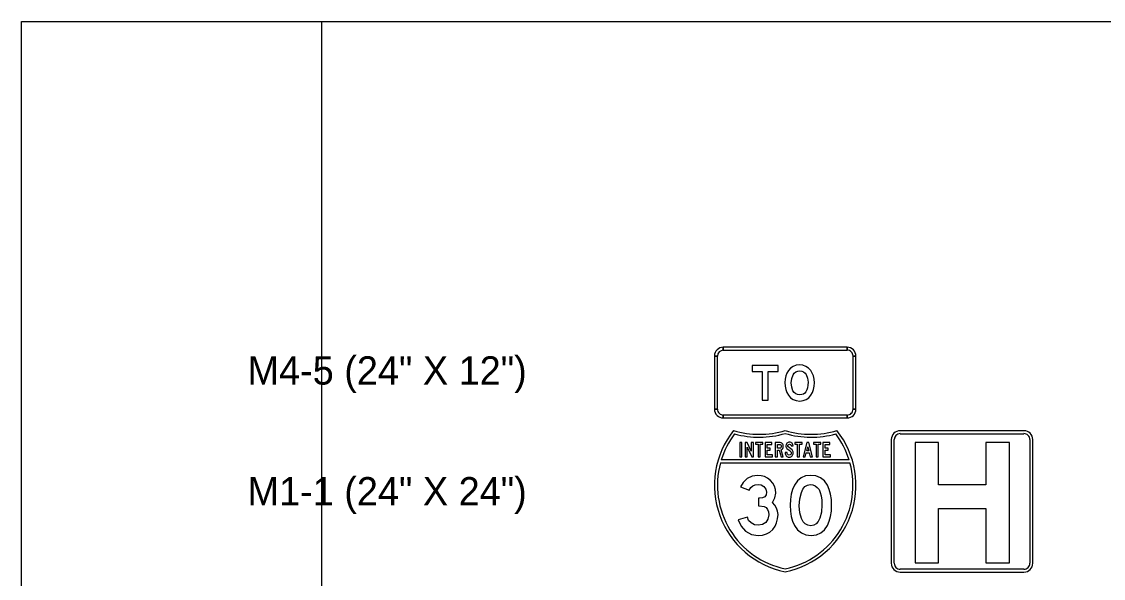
# Model space of a CAD drawing. Extents: x 1001568 to 1002149, y 1840825 to 1841423.
# Drawn here: x 1001886.41 to 1001901.7, y 1841302.79 to 1841310.67 of the extents above; entities that cross this region are included whole.
import ezdxf

# ---------------------------------------------------------------- set-up
doc = ezdxf.new("R2010")
doc.units = 0
for name, color, linetype in [('40', 7, 'Continuous'), ('R_No Plot', 7, 'Continuous'), ('SIGNS', 7, 'Continuous')]:
    doc.layers.add(name, color=color, linetype=linetype)

msp = doc.modelspace()

# ---------------------------------------------------------------- linework, layer by layer
at = {"layer": 'R_No Plot'}
msp.add_line((1001890.65, 1841310.667), (1001890.65, 1841248.127), dxfattribs=at)
msp.add_lwpolyline([(1001886.411, 1841310.667), (1001964.232, 1841310.667), (1001964.232, 1841307.694), (1001968.454, 1841307.694), (1001968.454, 1841306.882), (1001982.133, 1841306.882), (1001982.133, 1841248.127), (1001886.411, 1841248.127)], close=True, dxfattribs=at)
at = {"layer": 'SIGNS'}
for p, q in [((1001898.081, 1841306.062), (1001896.331, 1841306.062)), ((1001896.331, 1841306.02), (1001896.331, 1841306.062)), ((1001898.081, 1841306.062), (1001898.081, 1841306.02)), ((1001896.206, 1841305.937), (1001896.206, 1841305.187)), ((1001896.206, 1841305.937), (1001896.247, 1841305.937)), ((1001898.164, 1841305.937), (1001898.206, 1841305.937)), ((1001898.206, 1841305.187), (1001898.206, 1841305.937)), ((1001896.247, 1841305.187), (1001896.206, 1841305.187)), ((1001896.331, 1841305.062), (1001896.331, 1841305.103)), ((1001898.081, 1841305.103), (1001898.081, 1841305.062)), ((1001898.206, 1841305.187), (1001898.164, 1841305.187)), ((1001896.331, 1841305.062), (1001898.081, 1841305.062)), ((1001900.581, 1841304.882), (1001898.831, 1841304.882)), ((1001900.581, 1841304.882), (1001898.831, 1841304.882)), ((1001898.831, 1841304.84), (1001900.581, 1841304.84)), ((1001896.594, 1841304.715), (1001896.565, 1841304.715)), ((1001896.565, 1841304.715), (1001896.565, 1841304.511)), ((1001896.594, 1841304.511), (1001896.594, 1841304.715)), ((1001896.668, 1841304.715), (1001896.64, 1841304.715)), ((1001896.64, 1841304.715), (1001896.64, 1841304.511)), ((1001896.724, 1841304.593), (1001896.668, 1841304.715)), ((1001896.668, 1841304.511), (1001896.668, 1841304.649)), ((1001896.668, 1841304.649), (1001896.733, 1841304.511)), ((1001896.756, 1841304.715), (1001896.724, 1841304.715)), ((1001896.724, 1841304.715), (1001896.724, 1841304.593)), ((1001896.756, 1841304.511), (1001896.756, 1841304.715)), ((1001896.891, 1841304.715), (1001896.786, 1841304.715)), ((1001896.786, 1841304.715), (1001896.786, 1841304.69)), ((1001896.786, 1841304.69), (1001896.823, 1841304.69)), ((1001896.823, 1841304.69), (1001896.823, 1841304.511)), ((1001896.853, 1841304.511), (1001896.853, 1841304.69)), ((1001896.853, 1841304.69), (1001896.891, 1841304.69)), ((1001896.891, 1841304.69), (1001896.891, 1841304.715)), ((1001897.019, 1841304.715), (1001896.921, 1841304.715)), ((1001896.921, 1841304.715), (1001896.921, 1841304.511)), ((1001896.951, 1841304.635), (1001896.951, 1841304.687)), ((1001896.951, 1841304.687), (1001897.019, 1841304.687)), ((1001896.994, 1841304.635), (1001896.951, 1841304.635)), ((1001896.994, 1841304.607), (1001896.994, 1841304.635)), ((1001897.019, 1841304.687), (1001897.019, 1841304.715)), ((1001897.218, 1841304.686), (1001897.214, 1841304.667)), ((1001897.214, 1841304.667), (1001897.215, 1841304.656)), ((1001897.215, 1841304.656), (1001897.218, 1841304.647)), ((1001897.229, 1841304.704), (1001897.218, 1841304.686)), ((1001897.218, 1841304.647), (1001897.223, 1841304.638)), ((1001897.223, 1841304.638), (1001897.23, 1841304.63)), ((1001897.237, 1841304.71), (1001897.229, 1841304.704)), ((1001897.23, 1841304.63), (1001897.263, 1841304.607)), ((1001897.246, 1841304.715), (1001897.237, 1841304.71)), ((1001897.242, 1841304.667), (1001897.244, 1841304.676)), ((1001897.244, 1841304.661), (1001897.242, 1841304.667)), ((1001897.244, 1841304.676), (1001897.25, 1841304.684)), ((1001897.247, 1841304.655), (1001897.244, 1841304.661)), ((1001897.256, 1841304.718), (1001897.246, 1841304.715)), ((1001897.263, 1841304.643), (1001897.247, 1841304.655)), ((1001897.25, 1841304.684), (1001897.258, 1841304.689)), ((1001897.266, 1841304.719), (1001897.256, 1841304.718)), ((1001897.258, 1841304.689), (1001897.267, 1841304.691)), ((1001897.286, 1841304.627), (1001897.263, 1841304.643)), ((1001897.278, 1841304.718), (1001897.266, 1841304.719)), ((1001897.267, 1841304.691), (1001897.277, 1841304.689)), ((1001897.277, 1841304.689), (1001897.285, 1841304.685)), ((1001897.288, 1841304.716), (1001897.278, 1841304.718)), ((1001897.285, 1841304.685), (1001897.289, 1841304.678)), ((1001897.302, 1841304.613), (1001897.286, 1841304.627)), ((1001897.297, 1841304.711), (1001897.288, 1841304.716)), ((1001897.289, 1841304.678), (1001897.292, 1841304.667)), ((1001897.292, 1841304.667), (1001897.32, 1841304.667)), ((1001897.305, 1841304.705), (1001897.297, 1841304.711)), ((1001897.315, 1841304.688), (1001897.305, 1841304.705)), ((1001897.32, 1841304.667), (1001897.315, 1841304.688)), ((1001897.445, 1841304.715), (1001897.34, 1841304.715)), ((1001897.34, 1841304.715), (1001897.34, 1841304.69)), ((1001897.34, 1841304.69), (1001897.377, 1841304.69)), ((1001897.377, 1841304.69), (1001897.377, 1841304.511)), ((1001897.407, 1841304.511), (1001897.407, 1841304.69)), ((1001897.407, 1841304.69), (1001897.445, 1841304.69)), ((1001897.445, 1841304.69), (1001897.445, 1841304.715)), ((1001897.71, 1841304.715), (1001897.605, 1841304.715)), ((1001897.605, 1841304.715), (1001897.605, 1841304.69)), ((1001897.605, 1841304.69), (1001897.642, 1841304.69)), ((1001897.642, 1841304.69), (1001897.642, 1841304.511)), ((1001897.672, 1841304.511), (1001897.672, 1841304.69)), ((1001897.672, 1841304.69), (1001897.71, 1841304.69)), ((1001897.71, 1841304.69), (1001897.71, 1841304.715)), ((1001897.837, 1841304.715), (1001897.74, 1841304.715)), ((1001897.74, 1841304.715), (1001897.74, 1841304.511)), ((1001897.77, 1841304.635), (1001897.77, 1841304.687)), ((1001897.77, 1841304.687), (1001897.837, 1841304.687)), ((1001897.813, 1841304.635), (1001897.77, 1841304.635)), ((1001897.813, 1841304.607), (1001897.813, 1841304.635)), ((1001897.837, 1841304.687), (1001897.837, 1841304.715)), ((1001898.706, 1841304.757), (1001898.706, 1841303.007)), ((1001898.706, 1841304.757), (1001898.706, 1841303.007)), ((1001898.747, 1841303.007), (1001898.747, 1841304.757)), ((1001899.375, 1841304.715), (1001899.042, 1841304.715)), ((1001899.042, 1841304.715), (1001899.042, 1841303.015)), ((1001899.375, 1841304.715), (1001899.042, 1841304.715)), ((1001899.042, 1841304.715), (1001899.042, 1841303.015)), ((1001899.375, 1841304.115), (1001899.375, 1841304.715)), ((1001899.375, 1841304.115), (1001899.375, 1841304.715)), ((1001900.375, 1841304.715), (1001900.042, 1841304.715)), ((1001900.042, 1841304.715), (1001900.042, 1841304.115)), ((1001900.375, 1841304.715), (1001900.042, 1841304.715)), ((1001900.042, 1841304.715), (1001900.042, 1841304.115)), ((1001900.375, 1841303.015), (1001900.375, 1841304.715)), ((1001900.375, 1841303.015), (1001900.375, 1841304.715)), ((1001900.664, 1841304.757), (1001900.664, 1841303.007)), ((1001900.706, 1841303.007), (1001900.706, 1841304.757)), ((1001900.706, 1841303.007), (1001900.706, 1841304.757)), ((1001898.11, 1841304.469), (1001896.302, 1841304.469)), ((1001896.565, 1841304.511), (1001896.594, 1841304.511)), ((1001896.64, 1841304.511), (1001896.668, 1841304.511)), ((1001896.733, 1841304.511), (1001896.756, 1841304.511)), ((1001896.823, 1841304.511), (1001896.853, 1841304.511)), ((1001896.921, 1841304.511), (1001897.026, 1841304.511)), ((1001896.951, 1841304.539), (1001896.951, 1841304.607)), ((1001896.951, 1841304.607), (1001896.994, 1841304.607)), ((1001897.026, 1841304.539), (1001896.951, 1841304.539)), ((1001897.026, 1841304.511), (1001897.026, 1841304.539)), ((1001897.233, 1841304.572), (1001897.205, 1841304.572)), ((1001897.205, 1841304.572), (1001897.205, 1841304.571)), ((1001897.205, 1841304.571), (1001897.206, 1841304.558)), ((1001897.206, 1841304.558), (1001897.209, 1841304.547)), ((1001897.209, 1841304.547), (1001897.214, 1841304.536)), ((1001897.214, 1841304.536), (1001897.221, 1841304.526)), ((1001897.221, 1841304.526), (1001897.229, 1841304.518)), ((1001897.229, 1841304.518), (1001897.239, 1841304.512)), ((1001897.235, 1841304.559), (1001897.233, 1841304.572)), ((1001897.24, 1841304.548), (1001897.235, 1841304.559)), ((1001897.239, 1841304.512), (1001897.25, 1841304.508)), ((1001897.25, 1841304.54), (1001897.24, 1841304.548)), ((1001897.263, 1841304.537), (1001897.25, 1841304.54)), ((1001897.25, 1841304.508), (1001897.263, 1841304.507)), ((1001897.263, 1841304.607), (1001897.275, 1841304.597)), ((1001897.274, 1841304.539), (1001897.263, 1841304.537)), ((1001897.263, 1841304.507), (1001897.275, 1841304.508)), ((1001897.284, 1841304.547), (1001897.274, 1841304.539)), ((1001897.275, 1841304.597), (1001897.283, 1841304.59)), ((1001897.275, 1841304.508), (1001897.286, 1841304.512)), ((1001897.283, 1841304.59), (1001897.29, 1841304.58)), ((1001897.29, 1841304.557), (1001897.284, 1841304.547)), ((1001897.286, 1841304.512), (1001897.296, 1841304.518)), ((1001897.29, 1841304.58), (1001897.292, 1841304.569)), ((1001897.292, 1841304.569), (1001897.29, 1841304.557)), ((1001897.296, 1841304.518), (1001897.304, 1841304.526)), ((1001897.31, 1841304.603), (1001897.302, 1841304.613)), ((1001897.304, 1841304.526), (1001897.311, 1841304.535)), ((1001897.315, 1841304.593), (1001897.31, 1841304.603)), ((1001897.311, 1841304.535), (1001897.316, 1841304.546)), ((1001897.319, 1841304.581), (1001897.315, 1841304.593)), ((1001897.316, 1841304.546), (1001897.319, 1841304.557)), ((1001897.32, 1841304.569), (1001897.319, 1841304.581)), ((1001897.319, 1841304.557), (1001897.32, 1841304.569)), ((1001897.377, 1841304.511), (1001897.407, 1841304.511)), ((1001897.642, 1841304.511), (1001897.672, 1841304.511)), ((1001897.74, 1841304.511), (1001897.845, 1841304.511)), ((1001897.77, 1841304.539), (1001897.77, 1841304.607)), ((1001897.77, 1841304.607), (1001897.813, 1841304.607)), ((1001897.845, 1841304.539), (1001897.77, 1841304.539)), ((1001897.845, 1841304.511), (1001897.845, 1841304.539)), ((1001900.042, 1841304.115), (1001899.375, 1841304.115)), ((1001900.042, 1841304.115), (1001899.375, 1841304.115)), ((1001899.375, 1841303.015), (1001899.375, 1841303.782)), ((1001899.375, 1841303.782), (1001900.042, 1841303.782)), ((1001899.375, 1841303.015), (1001899.375, 1841303.782)), ((1001899.375, 1841303.782), (1001900.042, 1841303.782)), ((1001900.042, 1841303.782), (1001900.042, 1841303.015)), ((1001900.042, 1841303.782), (1001900.042, 1841303.015)), ((1001899.042, 1841303.015), (1001899.375, 1841303.015)), ((1001899.042, 1841303.015), (1001899.375, 1841303.015)), ((1001900.042, 1841303.015), (1001900.375, 1841303.015)), ((1001900.042, 1841303.015), (1001900.375, 1841303.015)), ((1001900.581, 1841302.924), (1001898.831, 1841302.924)), ((1001898.831, 1841302.882), (1001900.581, 1841302.882)), ((1001898.831, 1841302.882), (1001900.581, 1841302.882))]:
    msp.add_line(p, q, dxfattribs=at)
for points in [[(1001898.081, 1841306.062), (1001896.331, 1841306.062), (1001896.331, 1841306.02), (1001898.081, 1841306.02), (1001898.081, 1841306.062), (1001898.081, 1841306.062)], [(1001896.206, 1841305.937), (1001896.206, 1841305.187), (1001896.247, 1841305.187), (1001896.247, 1841305.937), (1001896.206, 1841305.937), (1001896.206, 1841305.937)], [(1001898.206, 1841305.187), (1001898.206, 1841305.937), (1001898.164, 1841305.937), (1001898.164, 1841305.187), (1001898.206, 1841305.187), (1001898.206, 1841305.187)], [(1001896.878, 1841305.312), (1001896.965, 1841305.312), (1001896.965, 1841305.72), (1001897.108, 1841305.72), (1001897.108, 1841305.802), (1001896.737, 1841305.802), (1001896.737, 1841305.72), (1001896.878, 1841305.72)], [(1001896.331, 1841305.062), (1001898.081, 1841305.062), (1001898.081, 1841305.103), (1001896.331, 1841305.103), (1001896.331, 1841305.062), (1001896.331, 1841305.062)], [(1001896.543, 1841303.622), (1001896.581, 1841303.531), (1001896.645, 1841303.461), (1001896.728, 1841303.416), (1001896.825, 1841303.401), (1001896.886, 1841303.407), (1001896.94, 1841303.422), (1001896.988, 1841303.449), (1001897.03, 1841303.486), (1001897.062, 1841303.53), (1001897.085, 1841303.579), (1001897.099, 1841303.634), (1001897.104, 1841303.695), (1001897.099, 1841303.744), (1001897.084, 1841303.789), (1001897.059, 1841303.829), (1001897.025, 1841303.865), (1001897.06, 1841303.934), (1001897.072, 1841304), (1001897.067, 1841304.051), (1001897.053, 1841304.098), (1001897.029, 1841304.14), (1001896.996, 1841304.179), (1001896.957, 1841304.21), (1001896.913, 1841304.233), (1001896.866, 1841304.246), (1001896.814, 1841304.251), (1001896.739, 1841304.239), (1001896.67, 1841304.205), (1001896.613, 1841304.152), (1001896.575, 1841304.087), (1001896.697, 1841304.042), (1001896.719, 1841304.077), (1001896.747, 1841304.102), (1001896.781, 1841304.117), (1001896.822, 1841304.122), (1001896.867, 1841304.115), (1001896.906, 1841304.092), (1001896.933, 1841304.056), (1001896.941, 1841304.012), (1001896.935, 1841303.974), (1001896.917, 1841303.948), (1001896.886, 1841303.933), (1001896.844, 1841303.93), (1001896.828, 1841303.93), (1001896.828, 1841303.818), (1001896.836, 1841303.818), (1001896.907, 1841303.812), (1001896.935, 1841303.794), (1001896.956, 1841303.769), (1001896.968, 1841303.735), (1001896.973, 1841303.693), (1001896.962, 1841303.633), (1001896.931, 1841303.586), (1001896.884, 1841303.555), (1001896.825, 1841303.545), (1001896.771, 1841303.553), (1001896.725, 1841303.577), (1001896.689, 1841303.613), (1001896.671, 1841303.66)]]:
    msp.add_lwpolyline(points, close=True, dxfattribs=at)
for points in [[(1001897.618, 1841305.561), (1001897.615, 1841305.61), (1001897.605, 1841305.656), (1001897.589, 1841305.697), (1001897.567, 1841305.734), (1001897.536, 1841305.768), (1001897.499, 1841305.792), (1001897.456, 1841305.807), (1001897.408, 1841305.812), (1001897.36, 1841305.807), (1001897.318, 1841305.792), (1001897.281, 1841305.768), (1001897.251, 1841305.734), (1001897.23, 1841305.698), (1001897.214, 1841305.658), (1001897.205, 1841305.612), (1001897.202, 1841305.563), (1001897.205, 1841305.512), (1001897.215, 1841305.465), (1001897.23, 1841305.423), (1001897.251, 1841305.385), (1001897.283, 1841305.348), (1001897.32, 1841305.323), (1001897.363, 1841305.307), (1001897.412, 1841305.302), (1001897.46, 1841305.307), (1001897.502, 1841305.322), (1001897.539, 1841305.348), (1001897.57, 1841305.384), (1001897.591, 1841305.421), (1001897.606, 1841305.463), (1001897.615, 1841305.51), (1001897.618, 1841305.561)], [(1001897.529, 1841305.567), (1001897.527, 1841305.526), (1001897.521, 1841305.49), (1001897.512, 1841305.459), (1001897.499, 1841305.434), (1001897.483, 1841305.415), (1001897.463, 1841305.401), (1001897.439, 1841305.393), (1001897.412, 1841305.39), (1001897.381, 1841305.394), (1001897.355, 1841305.404), (1001897.334, 1841305.422), (1001897.316, 1841305.447), (1001897.298, 1841305.497), (1001897.291, 1841305.561), (1001897.298, 1841305.622), (1001897.317, 1841305.672), (1001897.334, 1841305.696), (1001897.356, 1841305.713), (1001897.382, 1841305.724), (1001897.412, 1841305.727), (1001897.44, 1841305.724), (1001897.465, 1841305.714), (1001897.486, 1841305.697), (1001897.503, 1841305.675), (1001897.522, 1841305.626), (1001897.529, 1841305.567)], [(1001896.475, 1841304.886), (1001896.475, 1841304.886)], [(1001896.491, 1841304.838), (1001896.491, 1841304.838)], [(1001897.206, 1841304.844), (1001897.206, 1841304.844)], [(1001897.921, 1841304.838), (1001897.921, 1841304.838)], [(1001897.936, 1841304.886), (1001897.936, 1841304.886)], [(1001897.095, 1841304.511), (1001897.095, 1841304.608), (1001897.122, 1841304.608), (1001897.149, 1841304.511), (1001897.178, 1841304.511), (1001897.149, 1841304.612), (1001897.161, 1841304.619), (1001897.171, 1841304.63), (1001897.177, 1841304.643), (1001897.178, 1841304.658), (1001897.178, 1841304.67), (1001897.175, 1841304.681), (1001897.171, 1841304.691), (1001897.165, 1841304.699), (1001897.157, 1841304.706), (1001897.147, 1841304.711), (1001897.136, 1841304.714), (1001897.124, 1841304.715), (1001897.063, 1841304.715), (1001897.063, 1841304.511), (1001897.095, 1841304.511)], [(1001897.095, 1841304.635), (1001897.095, 1841304.687), (1001897.125, 1841304.687), (1001897.136, 1841304.686), (1001897.144, 1841304.68), (1001897.149, 1841304.672), (1001897.151, 1841304.661), (1001897.15, 1841304.65), (1001897.145, 1841304.642), (1001897.137, 1841304.637), (1001897.126, 1841304.635), (1001897.095, 1841304.635)], [(1001897.489, 1841304.511), (1001897.502, 1841304.567), (1001897.546, 1841304.567), (1001897.561, 1841304.511), (1001897.591, 1841304.511), (1001897.539, 1841304.715), (1001897.51, 1841304.715), (1001897.459, 1841304.511), (1001897.489, 1841304.511)], [(1001897.51, 1841304.596), (1001897.524, 1841304.656), (1001897.539, 1841304.596), (1001897.51, 1841304.596)], [(1001896.29, 1841304.428), (1001896.832, 1841304.428), (1001897.359, 1841304.428), (1001898.122, 1841304.428)], [(1001897.566, 1841304.251), (1001897.494, 1841304.242), (1001897.433, 1841304.216), (1001897.38, 1841304.172), (1001897.338, 1841304.111), (1001897.311, 1841304.051), (1001897.292, 1841303.984), (1001897.28, 1841303.91), (1001897.277, 1841303.83), (1001897.28, 1841303.746), (1001897.292, 1841303.669), (1001897.311, 1841303.601), (1001897.338, 1841303.541), (1001897.381, 1841303.48), (1001897.435, 1841303.436), (1001897.499, 1841303.41), (1001897.573, 1841303.401), (1001897.646, 1841303.41), (1001897.709, 1841303.437), (1001897.762, 1841303.481), (1001897.804, 1841303.543), (1001897.829, 1841303.601), (1001897.847, 1841303.668), (1001897.858, 1841303.742), (1001897.862, 1841303.825), (1001897.858, 1841303.91), (1001897.847, 1841303.986), (1001897.829, 1841304.053), (1001897.803, 1841304.112), (1001897.76, 1841304.173), (1001897.706, 1841304.216), (1001897.641, 1841304.242), (1001897.566, 1841304.251)], [(1001897.725, 1841303.833), (1001897.718, 1841303.732), (1001897.697, 1841303.647), (1001897.674, 1841303.599), (1001897.645, 1841303.565), (1001897.609, 1841303.544), (1001897.568, 1841303.538), (1001897.526, 1841303.544), (1001897.49, 1841303.563), (1001897.46, 1841303.595), (1001897.436, 1841303.64), (1001897.412, 1841303.723), (1001897.405, 1841303.822), (1001897.412, 1841303.92), (1001897.434, 1841304.007), (1001897.457, 1841304.057), (1001897.485, 1841304.093), (1001897.519, 1841304.114), (1001897.558, 1841304.121), (1001897.597, 1841304.117), (1001897.631, 1841304.103), (1001897.66, 1841304.081), (1001897.684, 1841304.049), (1001897.702, 1841304.008), (1001897.715, 1841303.959), (1001897.723, 1841303.9), (1001897.725, 1841303.833)], [(1001897.206, 1841302.928), (1001897.206, 1841302.928)], [(1001897.206, 1841302.886), (1001897.206, 1841302.886)]]:
    msp.add_lwpolyline(points, dxfattribs=at)
for centre, radius, start, end in [((1001896.331, 1841305.937), 0.125, 90.0002, 179.9998), ((1001896.331, 1841305.937), 0.125, 90.0002, 179.9998), ((1001896.331, 1841305.937), 0.0833, 90.0002, 179.9998), ((1001898.081, 1841305.937), 0.125, 360, 90.0002), ((1001898.081, 1841305.937), 0.125, 360, 90.0002), ((1001898.081, 1841305.937), 0.0833, 360, 90.0002), ((1001896.331, 1841305.187), 0.125, 179.9998, 270.0001), ((1001896.331, 1841305.187), 0.125, 179.9998, 270.0001), ((1001896.331, 1841305.187), 0.0833, 179.9998, 270.0001), ((1001898.081, 1841305.187), 0.125, 270.0001, 0.0003), ((1001898.081, 1841305.187), 0.125, 270.0001, 0.0003), ((1001898.081, 1841305.187), 0.0833, 270.0001, 0.0003), ((1001897.456, 1841304.111), 1.25, 141.669, 258.463), ((1001897.456, 1841304.11), 1.208, 142.9959, 162.6952), ((1001896.841, 1841306.081), 1.25, 253.009, 286.9909), ((1001896.837, 1841306.082), 1.292, 254.4391, 286.5746), ((1001896.956, 1841304.111), 1.25, 281.5371, 38.3311), ((1001897.571, 1841306.081), 1.25, 253.0091, 286.9911), ((1001897.574, 1841306.082), 1.292, 253.4255, 285.561), ((1001896.956, 1841304.11), 1.208, 17.3047, 37.0041), ((1001898.831, 1841304.757), 0.125, 90.0002, 179.9998), ((1001898.831, 1841304.757), 0.125, 90.0002, 179.9998), ((1001898.831, 1841304.757), 0.0833, 90.0002, 179.9998), ((1001900.581, 1841304.757), 0.125, 0, 90.0002), ((1001900.581, 1841304.757), 0.125, 0, 90.0002), ((1001900.581, 1841304.757), 0.0833, 0, 90.0002), ((1001897.456, 1841304.11), 1.208, 164.7534, 258.0704), ((1001896.956, 1841304.11), 1.208, 281.9296, 15.2467), ((1001898.831, 1841303.007), 0.125, 179.9998, 270.0001), ((1001898.831, 1841303.007), 0.125, 179.9998, 270.0001), ((1001898.831, 1841303.007), 0.0833, 179.9998, 270.0001), ((1001900.581, 1841303.007), 0.125, 270.0001, 0.0003), ((1001900.581, 1841303.007), 0.125, 270.0001, 0.0003), ((1001900.581, 1841303.007), 0.0833, 270.0001, 0.0003), ((1001896.956, 1841304.11), 1.208, 281.92961267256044, 281.92963936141), ((1001897.456, 1841304.11), 1.208, 258.0704, 258.0705)]:
    msp.add_arc(centre, radius, start, end, dxfattribs=at)

# ---------------------------------------------------------------- texts
at = {"layer": '40'}
for s, p in [('M4-5 (24" X 12")', (1001889.605, 1841305.534)), ('M1-1 (24" X 24")', (1001889.605, 1841303.826))]:
    msp.add_text(s, height=0.4, rotation=0, dxfattribs=at).set_placement(p)

doc.saveas('drawing.dxf')
